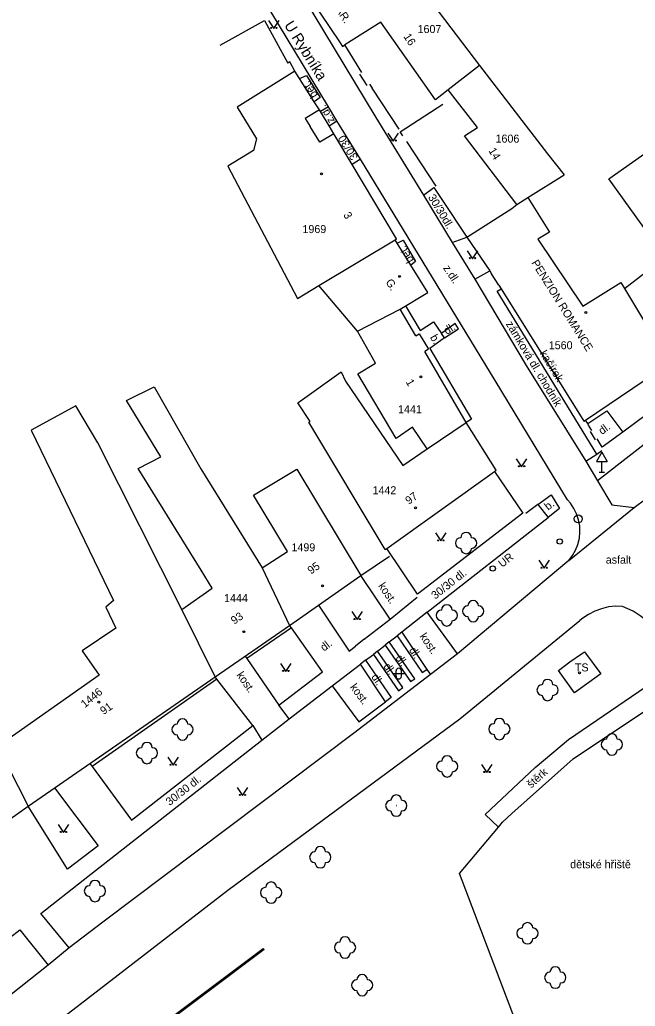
# Model space of a CAD drawing. Extents: x -584400 to -581602, y -1210894 to -1208793.
# Drawn here: x -582615.8 to -582558.1, y -1209339.9 to -1209247.4 of the extents above; entities that cross this region are included whole.
import ezdxf

# ---------------------------------------------------------------- set-up
doc = ezdxf.new("R2010")
doc.units = 0
for name, color, linetype in [('BUDOVY_MĚŘ', 7, 'Continuous'), ('MAP_ZN_BP', 7, 'Continuous'), ('NÁZVY_ULIC_TOK_SMĚR', 7, 'Continuous'), ('POMOC_POPIS', 7, 'Continuous'), ('ROZHRANÍ_PLOCH', 7, 'Continuous'), ('ZELEŇ', 7, 'Continuous'), ('ZN_BUDOV', 7, 'Continuous'), ('ZN_DOPLŇKOVÉ', 7, 'Continuous'), ('ZN_KULTUR', 7, 'Continuous'), ('Č_POPIS_EVID', 7, 'Continuous')]:
    doc.layers.add(name, color=color, linetype=linetype)

msp = doc.modelspace()

# ---------------------------------------------------------------- linework, layer by layer
at = {"layer": 'BUDOVY_MĚŘ'}
for points in [[(-582581.4, -1209240.19), (-582581.2, -1209240.06), (-582579.56, -1209242.22), (-582579.75, -1209242.35), (-582572.68, -1209251.66)], [(-582575.63, -1209253.95), (-582576.83, -1209254.89), (-582581.94, -1209247.59), (-582585.31, -1209249.72)], [(-582585.82, -1209249.44), (-582585.54, -1209249.87), (-582585.31, -1209249.72)], [(-582572.68, -1209251.66), (-582575.63, -1209253.95)], [(-582572.68, -1209251.66), (-582566.31, -1209259.93), (-582564.77, -1209261.92)], [(-582590, -1209252.2), (-582595.4, -1209255.57), (-582593.61, -1209258.53), (-582593.88, -1209259.64), (-582596.28, -1209261.09), (-582589.75, -1209273.49), (-582587.75, -1209272.29)], [(-582589.56, -1209252.89), (-582590, -1209252.2)], [(-582569.2, -1209264.69), (-582574.09, -1209258.26), (-582572.88, -1209257.46), (-582575.63, -1209253.95)], [(-582587.7, -1209255.83), (-582588.18, -1209255.07)], [(-582587.7, -1209255.83), (-582589.03, -1209256.62)], [(-582586.34, -1209258.06), (-582586.79, -1209257.32), (-582587.61, -1209255.98), (-582587.7, -1209255.83)], [(-582586.34, -1209258.06), (-582587.67, -1209258.85), (-582588.56, -1209257.39)], [(-582580.4, -1209268.31), (-582580.59, -1209268), (-582580.47, -1209267.91), (-582584.63, -1209260.94), (-582586.34, -1209258.06)], [(-582559.09, -1209272.55), (-582555.28, -1209269.64), (-582560.57, -1209262.28), (-582556.14, -1209259.16), (-582553.07, -1209263.5)], [(-582568.16, -1209264.04), (-582564.77, -1209261.92)], [(-582569.65, -1209265.07), (-582569.2, -1209264.69)], [(-582569.2, -1209264.69), (-582568.16, -1209264.04)], [(-582568.16, -1209264.04), (-582566.14, -1209267.28), (-582567.21, -1209267.95), (-582563.02, -1209274.21), (-582559.43, -1209272), (-582559.09, -1209272.55)], [(-582573.87, -1209267.75), (-582569.65, -1209265.07)], [(-582570.88, -1209272.25), (-582570.67, -1209272.59), (-582562.92, -1209285.01), (-582562.76, -1209284.9), (-582555.03, -1209279.69), (-582554.87, -1209279.58), (-582546.61, -1209273.42), (-582544.42, -1209271.81), (-582544.26, -1209271.69), (-582537.66, -1209266.82)], [(-582587.75, -1209272.29), (-582580.59, -1209268)], [(-582573.87, -1209267.75), (-582571.73, -1209270.92), (-582571.56, -1209271.19)], [(-582578.67, -1209277.01), (-582580.13, -1209274.5), (-582577.53, -1209272.94), (-582579.12, -1209270.38)], [(-582584.13, -1209276.58), (-582587.75, -1209272.29)], [(-582559.09, -1209272.55), (-582554.87, -1209279.58)], [(-582584.13, -1209276.58), (-582580.13, -1209274.5)], [(-582577.59, -1209287.6), (-582578.97, -1209285.56), (-582580.52, -1209286.62), (-582584.1, -1209280.55), (-582582.43, -1209279.55), (-582584.13, -1209276.58)], [(-582578.67, -1209277.01), (-582578.35, -1209276.82), (-582577.47, -1209278.25), (-582577.82, -1209278.46)], [(-582581.53, -1209297.04), (-582581.39, -1209296.94), (-582571.29, -1209289.73), (-582571.12, -1209289.61), (-582573.94, -1209285.12), (-582577.82, -1209278.46)], [(-582581.53, -1209297.04), (-582588.69, -1209285.09), (-582588.58, -1209285.02), (-582589.72, -1209283.28), (-582585.67, -1209280.37), (-582585.27, -1209281.26), (-582579.89, -1209289.16), (-582577.59, -1209287.6)], [(-582600.61, -1209302.66), (-582597.75, -1209300.65), (-582598.8, -1209298.98), (-582604.68, -1209289.45), (-582602.56, -1209288.33), (-582605.78, -1209283.06), (-582603.2, -1209281.77), (-582598.81, -1209289.46), (-582593.08, -1209298.75)], [(-582600.61, -1209302.66), (-582608.47, -1209287.04), (-582610.53, -1209283.57), (-582614.72, -1209285.85), (-582607, -1209301.81), (-582607.73, -1209302.43), (-582606.77, -1209304.4), (-582609.94, -1209306.52), (-582608.36, -1209308.81), (-582617.89, -1209315.5), (-582614.99, -1209321.09)], [(-582577.59, -1209287.6), (-582573.94, -1209285.12)], [(-582593.08, -1209298.75), (-582590.69, -1209297.22), (-582593.88, -1209291.95), (-582589.82, -1209289.51), (-582583.81, -1209299.48)], [(-582593.08, -1209298.75), (-582590.49, -1209304.15)], [(-582614.99, -1209321.09), (-582597.48, -1209308.98), (-582590.49, -1209304.15), (-582583.81, -1209299.48)], [(-582597.48, -1209308.98), (-582600.61, -1209302.66)], [(-582565.28, -1209308.36), (-582564.21, -1209307.55), (-582563.12, -1209306.8), (-582562.84, -1209306.61), (-582561.33, -1209308.7), (-582563.78, -1209310.47), (-582565.28, -1209308.36)], [(-582620.93, -1209325.27), (-582614.99, -1209321.09)]]:
    msp.add_lwpolyline(points, dxfattribs=at)
at = {"layer": 'MAP_ZN_BP'}
for radius in [0.375, 0.0005]:
    msp.add_circle((-582563.43, -1209294.16), radius, dxfattribs=at)
at = {"layer": 'ROZHRANÍ_PLOCH'}
for points in [[(-582592.21, -1209240.27), (-582582.4, -1209256.53), (-582577.93, -1209263.82)], [(-582586.86, -1209255.52), (-582594.59, -1209242.7)], [(-582589.56, -1209252.89), (-582588.9, -1209252.6), (-582587.62, -1209254.65), (-582588.18, -1209255.07)], [(-582586.86, -1209255.52), (-582587.61, -1209255.98)], [(-582586.07, -1209256.86), (-582586.86, -1209255.52)], [(-582586.79, -1209257.32), (-582586.07, -1209256.86)], [(-582583.85, -1209260.44), (-582586.07, -1209256.86)], [(-582583.85, -1209260.44), (-582584.63, -1209260.94)], [(-582564.31, -1209298.06), (-582563.96, -1209297.6), (-582563.68, -1209297.09), (-582563.47, -1209296.55), (-582563.33, -1209295.98), (-582563.28, -1209295.4), (-582563.3, -1209294.82), (-582563.41, -1209294.25), (-582563.59, -1209293.7), (-582563.85, -1209293.18), (-582564.17, -1209292.69), (-582564.43, -1209292.39), (-582571.23, -1209281.18), (-582583.85, -1209260.44)], [(-582577.93, -1209263.82), (-582576.98, -1209263.09)], [(-582577.93, -1209263.82), (-582575.25, -1209268.25)], [(-582580.4, -1209268.31), (-582579.84, -1209268.02), (-582578.69, -1209270.04), (-582579.12, -1209270.38)], [(-582575.25, -1209268.25), (-582573.87, -1209267.75)], [(-582575.25, -1209268.25), (-582573.14, -1209271.7)], [(-582573.14, -1209271.7), (-582571.73, -1209270.92)], [(-582573.14, -1209271.7), (-582568.31, -1209279.77), (-582562.74, -1209288.75)], [(-582561.7, -1209288.08), (-582571.03, -1209272.82), (-582570.67, -1209272.59)], [(-582579.64, -1209274.2), (-582578.27, -1209276.49), (-582577.02, -1209275.7), (-582576.27, -1209276.77)], [(-582575.98, -1209277.18), (-582574.67, -1209276.36), (-582574.98, -1209275.86), (-582576.27, -1209276.77)], [(-582575.98, -1209277.18), (-582576.27, -1209276.77)], [(-582575.98, -1209277.18), (-582577.34, -1209278.2), (-582573.44, -1209284.82), (-582573.94, -1209285.12)], [(-582552.15, -1209283.21), (-582561.64, -1209290.61)], [(-582562.55, -1209285.23), (-582560.75, -1209284.02), (-582559.26, -1209286.02)], [(-582562.32, -1209285.98), (-582561.84, -1209286.76)], [(-582558.19, -1209293.11), (-582549.44, -1209286.59)], [(-582561.7, -1209288.08), (-582561.24, -1209287.74)], [(-582562.74, -1209288.75), (-582561.7, -1209288.08)], [(-582562.74, -1209288.75), (-582561.64, -1209290.61)], [(-582561.64, -1209290.61), (-582560.3, -1209292.84), (-582558.19, -1209293.11)], [(-582567.22, -1209292.8), (-582565.97, -1209291.9), (-582565.2, -1209293.19), (-582566.25, -1209294.03)], [(-582567.22, -1209292.8), (-582568.36, -1209293.67)], [(-582567.22, -1209292.8), (-582566.25, -1209294.03)], [(-582564.31, -1209298.06), (-582558.19, -1209293.11)], [(-582577.6, -1209302.92), (-582566.25, -1209294.03)], [(-582564.31, -1209298.06), (-582574.74, -1209306.81)], [(-582581.07, -1209303.56), (-582583.81, -1209299.48)], [(-582581.07, -1209303.56), (-582578.53, -1209301.51)], [(-582587.79, -1209302.26), (-582584.9, -1209306.55), (-582584.32, -1209306.1)], [(-582545.03, -1209320.46), (-582554.24, -1209307.41), (-582555.49, -1209305.5), (-582555.94, -1209304.86), (-582556.45, -1209304.26), (-582557.02, -1209303.72), (-582557.64, -1209303.24), (-582558.3, -1209302.82), (-582559.29, -1209302.36), (-582559.95, -1209302.35), (-582560.61, -1209302.42), (-582561.26, -1209302.58), (-582561.88, -1209302.81), (-582562.46, -1209303.11), (-582563.01, -1209303.48), (-582563.29, -1209303.7)], [(-582583.49, -1209305.45), (-582581.07, -1209303.56)], [(-582577.6, -1209302.92), (-582579.98, -1209304.77)], [(-582574.74, -1209306.81), (-582577.6, -1209302.92)], [(-582596.29, -1209328.96), (-582574.53, -1209312.92), (-582563.29, -1209303.7)], [(-582590.33, -1209304.37), (-582594.49, -1209307.25)], [(-582591.49, -1209311.63), (-582587.42, -1209308.5), (-582590.33, -1209304.37)], [(-582590.33, -1209304.37), (-582590.49, -1209304.15)], [(-582583.49, -1209305.45), (-582584.32, -1209306.1)], [(-582581.15, -1209305.69), (-582580.42, -1209305.12)], [(-582579.98, -1209304.77), (-582580.42, -1209305.12)], [(-582580.42, -1209305.12), (-582578.06, -1209308.56), (-582577.62, -1209308.27)], [(-582579.98, -1209304.77), (-582577.62, -1209308.27)], [(-582582.27, -1209306.57), (-582581.54, -1209305.99)], [(-582581.54, -1209305.99), (-582579.15, -1209309.4), (-582578.76, -1209309.14), (-582581.15, -1209305.69)], [(-582581.15, -1209305.69), (-582581.54, -1209305.99)], [(-582574.74, -1209306.81), (-582584.52, -1209314.28), (-582608.01, -1209331.98)], [(-582594.65, -1209307.02), (-582594.49, -1209307.25)], [(-582594.49, -1209307.25), (-582591.49, -1209311.63)], [(-582583.37, -1209307.42), (-582582.64, -1209306.86)], [(-582582.64, -1209306.86), (-582580.28, -1209310.28), (-582579.89, -1209309.98), (-582582.27, -1209306.57)], [(-582582.27, -1209306.57), (-582582.64, -1209306.86)], [(-582586.5, -1209309.8), (-582583.84, -1209307.78)], [(-582583.37, -1209307.42), (-582583.84, -1209307.78)], [(-582581.52, -1209311.32), (-582583.84, -1209307.78)], [(-582583.37, -1209307.42), (-582580.96, -1209310.9), (-582581.52, -1209311.32)], [(-582597.31, -1209309.2), (-582597.48, -1209308.98)], [(-582577.62, -1209308.27), (-582577.29, -1209308.76)], [(-582597.31, -1209309.2), (-582609.01, -1209317.36)], [(-582593.93, -1209313.54), (-582597.31, -1209309.2)], [(-582590.55, -1209312.9), (-582586.5, -1209309.8)], [(-582586.5, -1209309.8), (-582584, -1209313.18), (-582581.52, -1209311.32)], [(-582570.92, -1209323.05), (-582572.15, -1209321.86), (-582567.49, -1209317.48), (-582564.34, -1209314.84), (-582556.48, -1209309.47), (-582555.28, -1209310.85), (-582555.72, -1209311.19)], [(-582590.55, -1209312.9), (-582591.49, -1209311.63)], [(-582609.01, -1209317.36), (-582605.31, -1209322.41), (-582593.93, -1209313.54)], [(-582593.93, -1209313.54), (-582593.1, -1209314.9)], [(-582593.1, -1209314.9), (-582590.55, -1209312.9)], [(-582609.85, -1209328.04), (-582593.1, -1209314.9)], [(-582609.21, -1209317.09), (-582609.01, -1209317.36)], [(-582612.52, -1209319.38), (-582608.44, -1209324.82), (-582611.32, -1209327)], [(-582611.32, -1209327), (-582614.99, -1209321.09)], [(-582611.17, -1209334.36), (-582613.81, -1209331.14), (-582609.85, -1209328.04)], [(-582635.34, -1209358.79), (-582615.47, -1209343.79), (-582596.29, -1209328.96)], [(-582608.01, -1209331.98), (-582611.17, -1209334.36)], [(-582669.69, -1209368.24), (-582664.16, -1209366.09), (-582660.21, -1209364.2), (-582646.46, -1209356.72), (-582632.47, -1209345.61), (-582622.32, -1209337.74), (-582620.45, -1209340.29), (-582617.99, -1209338.11), (-582619.69, -1209335.7), (-582615.78, -1209332.67), (-582613.13, -1209335.99)], [(-582611.17, -1209334.36), (-582613.13, -1209335.99)], [(-582613.13, -1209335.99), (-582641.19, -1209358.21), (-582647.89, -1209363.21), (-582654.54, -1209368.27), (-582661.14, -1209373.39), (-582667.7, -1209378.58), (-582673.24, -1209383.05)]]:
    msp.add_lwpolyline(points, dxfattribs=at)
at = {"layer": 'ZELEŇ'}
for centre in [(-582573.95, -1209296.43), (-582575.75, -1209303.21), (-582573.29, -1209302.81), (-582566.31, -1209310.21), (-582600.54, -1209313.91), (-582570.83, -1209313.86), (-582560.28, -1209315.31), (-582603.87, -1209316.11), (-582575.72, -1209317.36), (-582580.49, -1209321.04), (-582587.62, -1209325.88), (-582608.74, -1209329.05), (-582592.23, -1209329.2), (-582568.2, -1209333.01), (-582585.3, -1209334.34), (-582565.59, -1209337.16), (-582583.69, -1209337.87)]:
    msp.add_circle(centre, 0.0005, dxfattribs=at)
for centre, start, end in [((-582574.45, -1209296.43), 89.99999, 269.99999), ((-582573.95, -1209295.93), 0, 179.99999), ((-582573.45, -1209296.43), 270, 89.99999), ((-582573.95, -1209296.93), 179.99999, 359.99999), ((-582575.75, -1209302.71), 0, 179.99999), ((-582573.79, -1209302.81), 89.99999, 269.99999), ((-582573.29, -1209302.31), 0, 179.99999), ((-582572.79, -1209302.81), 270, 89.99999), ((-582576.25, -1209303.21), 89.99999, 269.99999), ((-582575.25, -1209303.21), 270, 89.99999), ((-582573.29, -1209303.31), 179.99999, 359.99999), ((-582575.75, -1209303.71), 179.99999, 359.99999), ((-582566.81, -1209310.21), 89.99999, 269.99999), ((-582566.31, -1209309.71), 0, 179.99999), ((-582565.81, -1209310.21), 270, 89.99999), ((-582566.31, -1209310.71), 179.99999, 359.99999), ((-582570.83, -1209313.36), 0, 179.99999), ((-582601.04, -1209313.91), 89.99999, 269.99999), ((-582600.54, -1209313.41), 0, 179.99999), ((-582600.04, -1209313.91), 270, 89.99999), ((-582571.33, -1209313.86), 89.99999, 269.99999), ((-582570.33, -1209313.86), 270, 89.99999), ((-582600.54, -1209314.41), 179.99999, 359.99999), ((-582570.83, -1209314.36), 179.99999, 359.99999), ((-582560.28, -1209314.81), 0, 179.99999), ((-582604.37, -1209316.11), 89.99999, 269.99999), ((-582603.87, -1209315.61), 0, 179.99999), ((-582603.37, -1209316.11), 270, 89.99999), ((-582560.78, -1209315.31), 89.99999, 269.99999), ((-582559.78, -1209315.31), 270, 89.99999), ((-582575.72, -1209316.86), 0, 179.99999), ((-582560.28, -1209315.81), 179.99999, 359.99999), ((-582603.87, -1209316.61), 179.99999, 359.99999), ((-582576.22, -1209317.36), 89.99999, 269.99999), ((-582575.22, -1209317.36), 270, 89.99999), ((-582575.72, -1209317.86), 179.99999, 359.99999), ((-582580.49, -1209320.54), 0, 179.99999), ((-582580.99, -1209321.04), 89.99999, 269.99999), ((-582579.99, -1209321.04), 270, 89.99999), ((-582580.49, -1209321.54), 179.99999, 359.99999), ((-582587.62, -1209325.38), 0, 179.99999), ((-582588.12, -1209325.88), 89.99999, 269.99999), ((-582587.12, -1209325.88), 270, 89.99999), ((-582587.62, -1209326.38), 179.99999, 359.99999), ((-582609.24, -1209329.05), 89.99999, 269.99999), ((-582608.74, -1209328.55), 0, 179.99999), ((-582608.24, -1209329.05), 270, 89.99999), ((-582592.23, -1209328.7), 0, 179.99999), ((-582592.73, -1209329.2), 89.99999, 269.99999), ((-582591.73, -1209329.2), 270, 89.99999), ((-582608.74, -1209329.55), 179.99999, 359.99999), ((-582592.23, -1209329.7), 179.99999, 359.99999), ((-582568.2, -1209332.51), 0, 179.99999), ((-582568.7, -1209333.01), 89.99999, 269.99999), ((-582567.7, -1209333.01), 270, 89.99999), ((-582585.8, -1209334.34), 89.99999, 269.99999), ((-582585.3, -1209333.84), 0, 179.99999), ((-582584.8, -1209334.34), 270, 89.99999), ((-582568.2, -1209333.51), 179.99999, 359.99999), ((-582585.3, -1209334.84), 179.99999, 359.99999), ((-582583.69, -1209337.37), 0, 179.99999), ((-582566.09, -1209337.16), 89.99999, 269.99999), ((-582565.59, -1209336.66), 0, 179.99999), ((-582565.09, -1209337.16), 270, 89.99999), ((-582584.19, -1209337.87), 89.99999, 269.99999), ((-582583.19, -1209337.87), 270, 89.99999), ((-582565.59, -1209337.66), 179.99999, 359.99999), ((-582583.69, -1209338.37), 179.99999, 359.99999)]:
    msp.add_arc(centre, 0.5, start, end, dxfattribs=at)
at = {"layer": 'ZN_BUDOV'}
for centre in [(-582587.5, -1209261.82), (-582580.18, -1209271.43), (-582562.72, -1209274.82), (-582578.18, -1209280.85), (-582578.7, -1209293.12), (-582587.4, -1209300.43), (-582594.78, -1209304.74), (-582563.31, -1209308.59), (-582608.37, -1209311.35)]:
    msp.add_circle(centre, 0.0875, dxfattribs=at)
at = {"layer": 'ZN_DOPLŇKOVÉ'}
for p, q in [((-582561.23, -1209287.904), (-582561.73, -1209288.77)), ((-582561.73, -1209288.77), (-582560.73, -1209288.77)), ((-582561.23, -1209287.904), (-582560.73, -1209288.77)), ((-582561.23, -1209289.77), (-582561.23, -1209288.77)), ((-582561.48, -1209289.77), (-582560.98, -1209289.77))]:
    msp.add_line(p, q, dxfattribs=at)
for points in [[(-582588.54, -1209245.39), (-582585.82, -1209249.44)], [(-582597, -1209249.75), (-582592.85, -1209247.43), (-582590.67, -1209251.43)], [(-582583.72, -1209252.31), (-582585.31, -1209249.72)], [(-582590.46, -1209251.31), (-582590.67, -1209251.43)], [(-582590, -1209252.2), (-582590.46, -1209251.31)], [(-582583.95, -1209252.46), (-582583.24, -1209253.55)], [(-582588.18, -1209255.07), (-582589.56, -1209252.89)], [(-582583, -1209253.4), (-582582.74, -1209253.8)], [(-582580.21, -1209257.64), (-582582.74, -1209253.8)], [(-582579.88, -1209258.24), (-582580.12, -1209257.88), (-582576.14, -1209255.28)], [(-582589.03, -1209256.62), (-582588.56, -1209257.39)], [(-582576.77, -1209262.96), (-582579.52, -1209258.79)], [(-582576.98, -1209263.09), (-582576.23, -1209264.22)], [(-582576.23, -1209264.22), (-582573.87, -1209267.75)], [(-582579.12, -1209270.38), (-582580.4, -1209268.31)], [(-582570.88, -1209272.25), (-582571.56, -1209271.19)], [(-582555.03, -1209279.69), (-582553.53, -1209281.77), (-582559.26, -1209286.02), (-582561.19, -1209287.45), (-582561.67, -1209286.66)], [(-582562.15, -1209285.88), (-582562.46, -1209285.39), (-582562.55, -1209285.23), (-582562.76, -1209284.9)], [(-582571.29, -1209289.73), (-582568.64, -1209293.63), (-582578.49, -1209301.23), (-582581.39, -1209296.94)], [(-582583.81, -1209299.48), (-582581.12, -1209297.65)], [(-582569.65, -1209321.78), (-582563.92, -1209316.65), (-582555.72, -1209311.19), (-582542.28, -1209331.14)], [(-582570.53, -1209322.59), (-582569.65, -1209321.78)], [(-582568.13, -1209344.34), (-582574.58, -1209327.39), (-582570.92, -1209323.05), (-582570.53, -1209322.59)], [(-582629.58, -1209366.16), (-582629.7, -1209366.24), (-582631.59, -1209363.58), (-582614.84, -1209350.85), (-582592.98, -1209334.42), (-582592.89, -1209334.54)], [(-582592.89, -1209334.54), (-582614.75, -1209350.97), (-582631.38, -1209363.62), (-582629.58, -1209366.16)]]:
    msp.add_lwpolyline(points, dxfattribs=at)
for centre, radius in [((-582565.171, -1209296.28), 0.25), ((-582565.171, -1209296.28), 0.0005), ((-582571.45, -1209298.81), 0.25), ((-582571.45, -1209298.81), 0.0005)]:
    msp.add_circle(centre, radius, dxfattribs=at)
at = {"layer": 'ZN_KULTUR'}
for p, q in [((-582580.77, -1209308.67), (-582579.77, -1209308.67)), ((-582580.52, -1209308.92), (-582580.52, -1209308.42)), ((-582580.02, -1209308.92), (-582580.02, -1209308.42))]:
    msp.add_line(p, q, dxfattribs=at)
for points in [[(-582592.47, -1209247.44), (-582591.97, -1209248.19), (-582591.47, -1209247.44)], [(-582581.29, -1209257.99), (-582580.79, -1209258.74), (-582580.29, -1209257.99)], [(-582573.85, -1209269.02), (-582573.35, -1209269.77), (-582572.85, -1209269.02)], [(-582569.24, -1209288.53), (-582568.74, -1209289.28), (-582568.24, -1209288.53)], [(-582576.82, -1209295.48), (-582576.32, -1209296.23), (-582575.82, -1209295.48)], [(-582567.13, -1209298.04), (-582566.63, -1209298.79), (-582566.13, -1209298.04)], [(-582584.66, -1209302.85), (-582584.16, -1209303.6), (-582583.66, -1209302.85)], [(-582591.35, -1209307.72), (-582590.85, -1209308.47), (-582590.35, -1209307.72)], [(-582601.9, -1209316.51), (-582601.4, -1209317.26), (-582600.9, -1209316.51)], [(-582572.49, -1209317.19), (-582571.99, -1209317.94), (-582571.49, -1209317.19)], [(-582595.42, -1209319.34), (-582594.92, -1209320.09), (-582594.42, -1209319.34)], [(-582612.2, -1209322.81), (-582611.7, -1209323.56), (-582611.2, -1209322.81)]]:
    msp.add_lwpolyline(points, dxfattribs=at)
for centre in [(-582592.22, -1209248.14), (-582591.72, -1209248.14), (-582581.04, -1209258.69), (-582580.54, -1209258.69), (-582573.6, -1209269.72), (-582573.1, -1209269.72), (-582568.99, -1209289.23), (-582568.49, -1209289.23), (-582576.57, -1209296.18), (-582576.07, -1209296.18), (-582566.88, -1209298.74), (-582566.38, -1209298.74), (-582584.41, -1209303.55), (-582583.91, -1209303.55), (-582591.1, -1209308.42), (-582590.6, -1209308.42), (-582601.65, -1209317.21), (-582601.15, -1209317.21), (-582572.24, -1209317.89), (-582571.74, -1209317.89), (-582595.17, -1209320.04), (-582594.67, -1209320.04), (-582611.95, -1209323.51), (-582611.45, -1209323.51)]:
    msp.add_circle(centre, 0.05, dxfattribs=at)
for centre, start, end in [((-582580.27, -1209308.42), 0, 179.99999), ((-582580.27, -1209308.92), 179.99999, 359.99999)]:
    msp.add_arc(centre, 0.25, start, end, dxfattribs=at)

# ---------------------------------------------------------------- texts
at = {"layer": 'NÁZVY_ULIC_TOK_SMĚR'}
msp.add_text('U Rybníka', height=1, rotation=301.79738, dxfattribs=at).set_placement((-582591.04, -1209247.87))
at = {"layer": 'POMOC_POPIS'}
for s, rotation, p in [('GAR.', 303.88553, (-582586.68, -1209245.75)), ('bet.', 121.98025, (-582587.83, -1209254.45)), ('z.dl.', 120.52156, (-582586.24, -1209256.84)), ('30/30', 121.80355, (-582584.05, -1209260.24)), ('30/30dl.', 301.17251, (-582577.55, -1209264)), ('bet.', 119.65318, (-582578.84, -1209269.93)), ('PENZION ROMANCE', 301.96388, (-582567.86, -1209270.16)), ('z.dl.', 303.20107, (-582576.13, -1209270.65)), ('G.', 301.79738, (-582581.53, -1209271.95)), ('dl.', 32.04467, (-582575.76, -1209276.92)), ('zámková dl. chodník', 300.90105, (-582570.25, -1209275.88)), ('b.', 300.21081, (-582577.36, -1209277.14)), ('kačírek', 301.44169, (-582567.08, -1209278.64)), ('dl.', 36.53597, (-582561.2, -1209286.31)), ('b.', 38.65981, (-582566.25, -1209293.4)), ('UR', 37.97805, (-582570.57, -1209298.76)), ('30/30 dl.', 38.15721, (-582576.85, -1209301.74)), ('kost.', 303.88409, (-582582.22, -1209300.44)), ('kost.', 303.98728, (-582578.34, -1209305.17)), ('dl.', 37.97438, (-582587.26, -1209306.62)), ('dl.', 304.45195, (-582579.34, -1209306.48)), ('dl.', 305.02583, (-582580.6, -1209307.21)), ('dl.', 304.60797, (-582581.74, -1209307.99)), ('kost.', 304.40847, (-582595.5, -1209308.8)), ('dl.', 303.23952, (-582582.87, -1209308.97)), ('kost.', 306.4883, (-582584.87, -1209309.94)), ('30/30 dl.', 38.12541, (-582601.74, -1209321.08)), ('štěrk', 41.83772, (-582567.85, -1209319.45))]:
    msp.add_text(s, height=0.75, rotation=rotation, dxfattribs=at).set_placement(p)
for s, p in [('asfalt', (-582560.86, -1209298.36)), ('TS', (-582563.75, -1209308.46)), ('dětské hřiště', (-582564.19, -1209326.91))]:
    msp.add_text(s, height=0.75, dxfattribs=at).set_placement(p)
at = {"layer": 'Č_POPIS_EVID'}
for s, p in [('1607', (-582578.5, -1209248.62)), ('1606', (-582571.19, -1209258.89)), ('1969', (-582589.29, -1209267.37)), ('1560', (-582566.2, -1209278.26)), ('1441', (-582580.33, -1209284.26)), ('1442', (-582582.72, -1209291.85)), ('1499', (-582590.32, -1209297.2)), ('1444', (-582596.64, -1209301.96))]:
    msp.add_text(s, height=0.75, dxfattribs=at).set_placement(p)
for s, rotation, p in [('16', 302.43881, (-582579.85, -1209248.94)), ('14', 301.71499, (-582571.88, -1209259.64)), ('3', 300.81402, (-582585.49, -1209265.66)), ('1', 300.21081, (-582579.63, -1209281.32)), ('97', 35.49703, (-582579.32, -1209292.85)), ('95', 34.94418, (-582588.49, -1209299.39)), ('93', 34.63673, (-582595.68, -1209304.09)), ('1446', 39.35596, (-582609.69, -1209311.92)), ('91', 34.67013, (-582607.94, -1209312.56))]:
    msp.add_text(s, height=0.75, rotation=rotation, dxfattribs=at).set_placement(p)

doc.saveas('drawing.dxf')
